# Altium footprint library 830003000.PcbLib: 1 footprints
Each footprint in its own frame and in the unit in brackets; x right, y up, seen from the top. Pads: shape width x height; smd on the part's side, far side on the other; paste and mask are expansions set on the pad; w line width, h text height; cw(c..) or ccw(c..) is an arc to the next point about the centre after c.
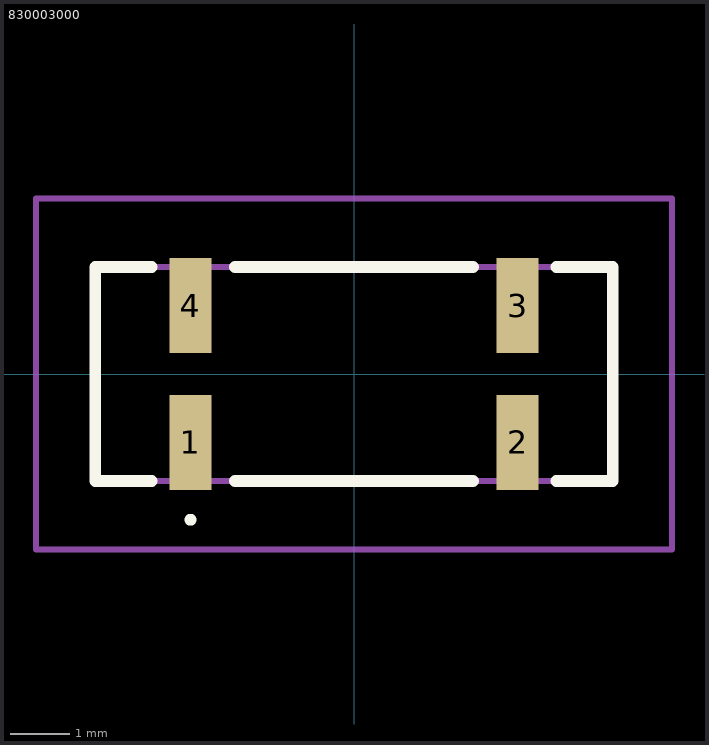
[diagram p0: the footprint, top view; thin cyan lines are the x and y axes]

## 830003000 [mm]
pads (4):
  rect 0.7x1.6 smd: 1(-2.75,-1.15) 2(2.75,-1.15) 3(2.75,1.15) 4(-2.75,1.15)
Top Overlay:
  lines w0.1: -2.75,-2.5 cw(c-2.75,-2.45) -2.75,-2.4 ; -2.75,-2.5 -2.75,-2.5 ; -2.75,-2.5 ccw(c-2.75,-2.45) -2.75,-2.4 ; -2.75,-2.4 -2.75,-2.4
  lines w0.2: -3.4,-1.8 -4.35,-1.8 -4.35,1.8 -3.4,1.8 ; -2,-1.8 2,-1.8 ; -2,1.8 2,1.8 ; 3.4,-1.8 4.35,-1.8 4.35,1.8 3.4,1.8
Mechanical 15:
  lines w0.1: -4.35,-1.8 4.35,-1.8 4.35,1.8 -4.35,1.8 -4.35,-1.8
Mechanical 20:
  lines w0.1: -5.35,-2.95 5.35,-2.95 5.35,2.95 -5.35,2.95 -5.35,-2.95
